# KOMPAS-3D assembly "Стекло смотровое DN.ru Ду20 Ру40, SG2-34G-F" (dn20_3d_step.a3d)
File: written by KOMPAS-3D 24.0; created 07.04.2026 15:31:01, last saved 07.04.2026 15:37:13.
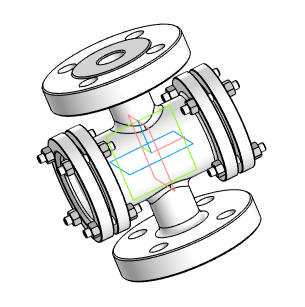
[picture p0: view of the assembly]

Document properties: Автор: Main; Полное имя файла: D:\DN.ru Аутсерс\Стекло смотровое DN.ru\Исходники\Стекло смотровое DN.ru SG2-34G-F тип В ГОСТ 21836-2021 Ду20 Ру40, углеродистая сталь, фланцевое\dn20_3d_step.a3d

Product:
- Component [detail]: Деталь  | qty 1  | pos. 1  | Масса: 3.673211; Автор: Main; additional columns: Типовые; source file: ДетальДеталь.m3d
- Component [detail]: Стекло  | qty 2  | pos. 2  | Масса: 0.08342; Автор: Main; source file: СтеклоСтекло.m3d
- Component [detail]: ANSI B18.2.4.2M - M6x1 - 10  | designation ANSI B18.2.4.2M - M6x1  | qty 16  | pos. 3  | Масса: 0.003008; Комментарий: Типы метрических   шестигранных гаек   2; Автор: Main; additional columns: Сталь, мягкая; source file: ANSI B18.2.4.2M - M6x1ANSI B18.2.4.2M - M6x1 - 10.m3d
- Part/product: Стекло смотровое DN.ru Ду20 Ру40  | designation SG2-34G-F
    Масса: 4.8
    Раздел спецификации: Прочие изделия
    Примечание: D500-00080

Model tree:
1. Массив по концентрической сетке:1  (labels: Грань.Твердое тело1; Ребро.Solid1; Ребро.Твердое тело1; Грань.Solid1)  (4 pattern instances)
     Шаг 2 = 360

Expressions: SG2-34G-F
Referenced files in D:\DN.ru Аутсерс\Стекло смотровое DN.ru\Исходники\Стекло смотровое DN.ru SG2-34G-F тип В ГОСТ 21836-2021 Ду20 Ру40, углеродистая сталь, фланцевое\: ДетальДеталь.m3d, СтеклоСтекло.m3d, ANSI B18.2.4.2M - M6x1ANSI B18.2.4.2M - M6x1 - 10.m3d
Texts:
  Стекло Стекло (1)
  Стекло Стекло (2)
  ANSI B18.2.4.2M - M6x1 ANSI B18.2.4.2M - M6x1 - 10 (1)
  ANSI B18.2.4.2M - M6x1 ANSI B18.2.4.2M - M6x1 - 10 (2)
  ANSI B18.2.4.2M - M6x1 ANSI B18.2.4.2M - M6x1 - 10 (3)
  ANSI B18.2.4.2M - M6x1 ANSI B18.2.4.2M - M6x1 - 10 (4)
  ANSI B18.2.4.2M - M6x1 ANSI B18.2.4.2M - M6x1 - 10 (5)
  ANSI B18.2.4.2M - M6x1 ANSI B18.2.4.2M - M6x1 - 10 (6)
  ANSI B18.2.4.2M - M6x1 ANSI B18.2.4.2M - M6x1 - 10 (7)
  ANSI B18.2.4.2M - M6x1 ANSI B18.2.4.2M - M6x1 - 10 (8)
  ANSI B18.2.4.2M - M6x1 ANSI B18.2.4.2M - M6x1 - 10 (9)
  ANSI B18.2.4.2M - M6x1 ANSI B18.2.4.2M - M6x1 - 10 (10)
  ANSI B18.2.4.2M - M6x1 ANSI B18.2.4.2M - M6x1 - 10 (11)
  ANSI B18.2.4.2M - M6x1 ANSI B18.2.4.2M - M6x1 - 10 (12)
  ANSI B18.2.4.2M - M6x1 ANSI B18.2.4.2M - M6x1 - 10 (13)
  ANSI B18.2.4.2M - M6x1 ANSI B18.2.4.2M - M6x1 - 10 (14)
  ANSI B18.2.4.2M - M6x1 ANSI B18.2.4.2M - M6x1 - 10 (15)
  ANSI B18.2.4.2M - M6x1 ANSI B18.2.4.2M - M6x1 - 10 (16)
  Ось Z.Начало координат
  Ось X.Начало координат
